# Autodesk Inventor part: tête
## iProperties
Created: 2002-09
Part Number: tête
Material: Par défaut
Document SubType Name: Modélisation
Designer: Maison
Control State: 0
Master: False
Checked Out: False
Shininess: 20.0
Length Units: 11269
Angle Units: 11279
Time Units: 11290
Mass Units: 11283
Length Display Precision: 3
Angle Display Precision: 2
Density: 0.0
Volumn: 0.0
Area: 0.0
PropertySet Name: Model Information
Author: Maison
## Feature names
1. Révolution1 [Revolution]
